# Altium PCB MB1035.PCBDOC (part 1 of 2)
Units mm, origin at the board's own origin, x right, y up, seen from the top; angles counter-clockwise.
Board outline 66 x 97 mm, 2 copper layers (TOP, Bottom), stack 1.535 mm thick; 147 components, 174 nets, 595 pads, 205 vias.
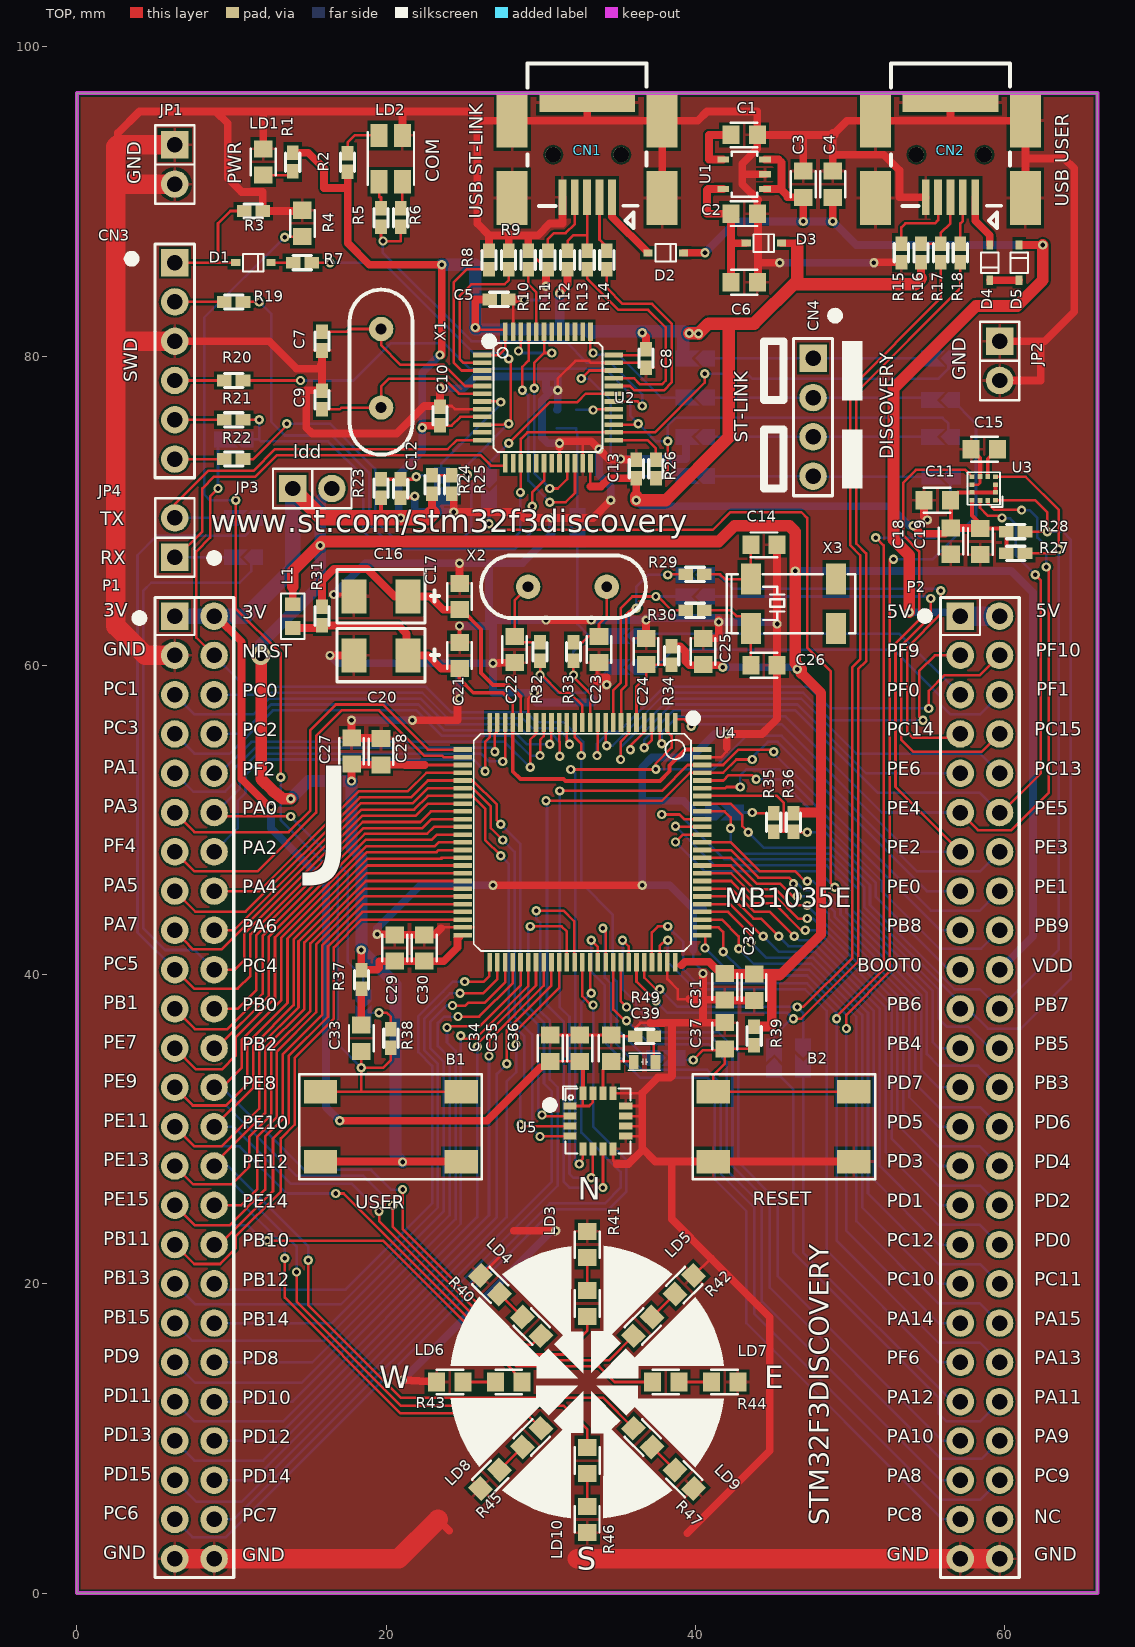
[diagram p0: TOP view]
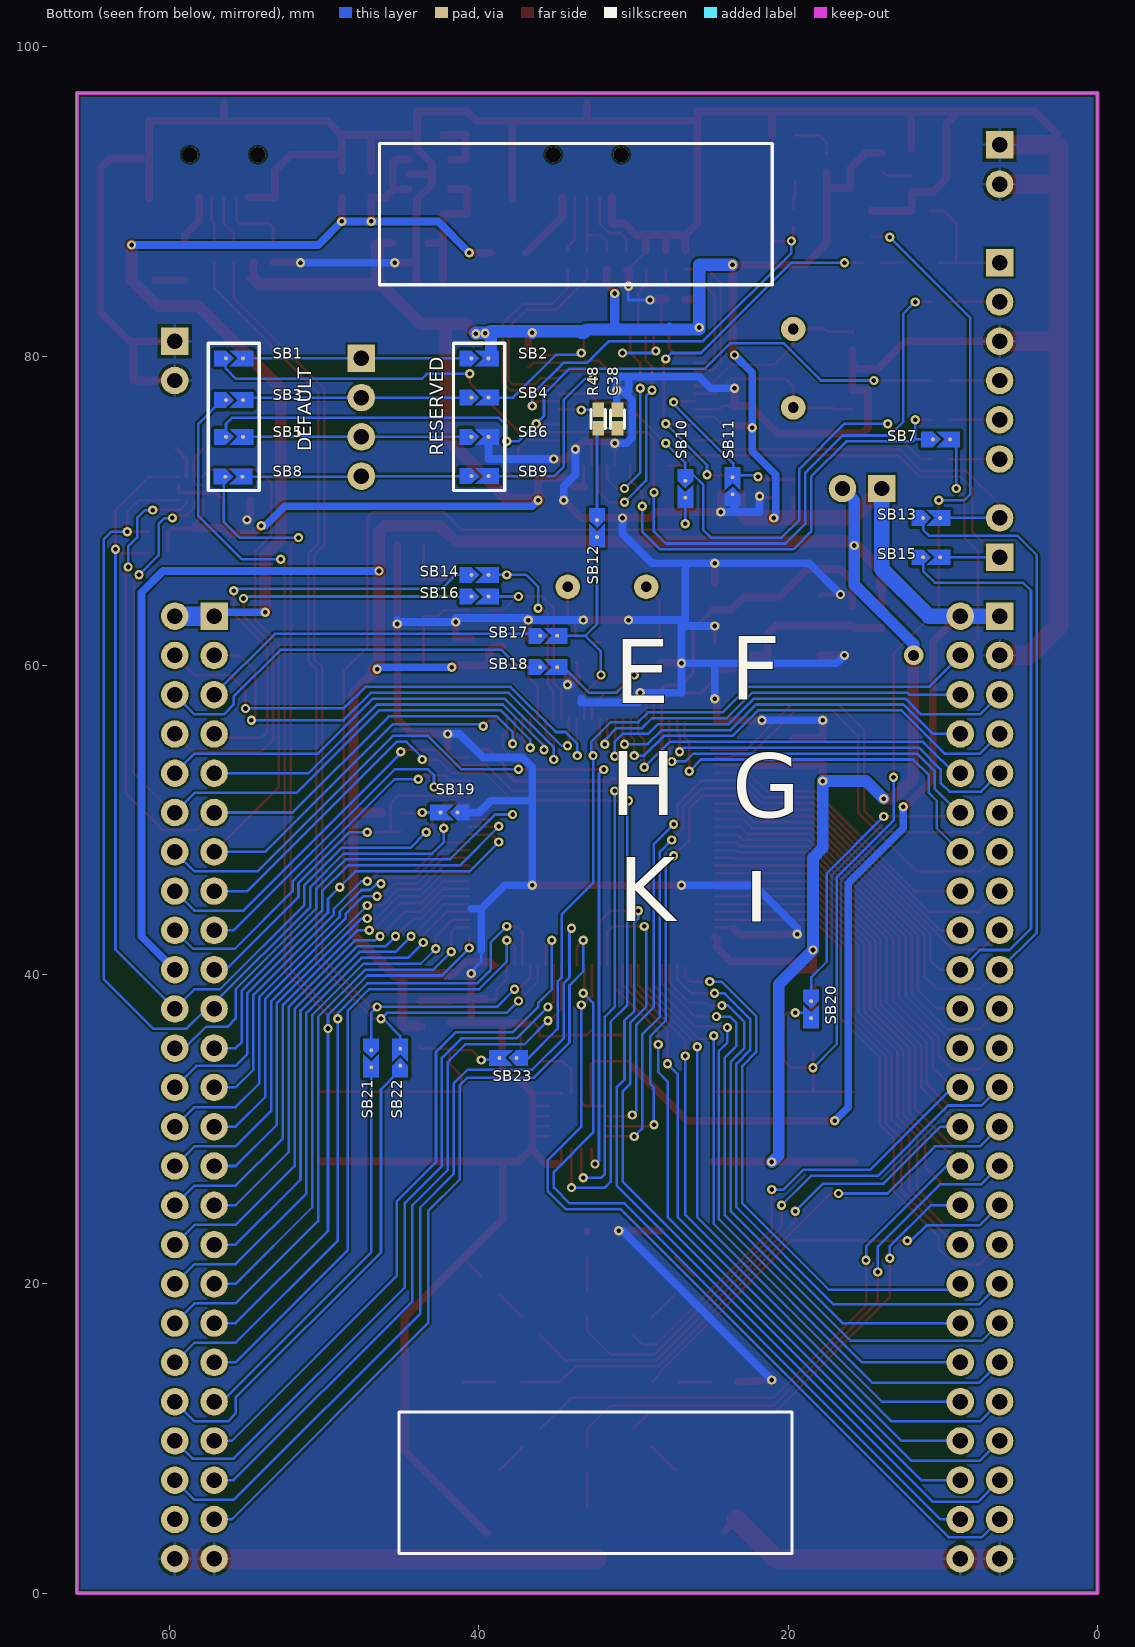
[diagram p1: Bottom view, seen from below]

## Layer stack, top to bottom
Top Mask: solder mask 0.0102, Solder Resist, Dk 3.5
TOP: signal copper 0.035
Dielectric 1: dielectric 1.465, FR-4, Dk 4.8
Bottom: signal copper 0.035
Bottom Solder: solder mask 0.0102, Solder Resist, Dk 3.5

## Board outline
0,0 66,0 66,97 0,97

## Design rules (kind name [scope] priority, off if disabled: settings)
Clearance [All] p1: gap=0.127 ignorepadtopadclearanceinfootprint=FALSE except(0: Arc-Hole Track-Hole SMDPad-Hole THPad-Hole Via-Hole Fill-Hole Poly-Hole Region-Hole Text-Hole; 0.2: SMDPad-Fill SMDPad-Poly SMDPad-Region Fill-Fill Fill-Poly Fill-Region Poly-Poly Poly-Region Region-Region)
ComponentClearance [All] p1: gap=0.2 collisioncheckmode=3 verticalgap=0.2 showdistances=FALSE
HoleSize [All] p1: absolutevalues=TRUE maxlimit=10 minlimit=0.025 maxpercent=80.000 minpercent=20.000
MinimumSolderMaskSliver [All] p1: minsoldermaskwidth=0.1
PlaneConnect [All] p1: planeconnectstyle=Relief reliefexpansion=0.508 reliefentries=4 reliefconductorwidth=0.21 reliefairgap=0.21
PolygonConnect PolygonConnect_via [IsVia] p1: connectstyle=Direct reliefconductorwidth=0.254 reliefentries=4 polygonreliefangle="90 Angle" airgapwidth=0.254
PolygonConnect [All] p2: connectstyle=Relief reliefconductorwidth=0.2 reliefentries=4 polygonreliefangle="90 Angle" airgapwidth=0.2
RoutingVias [All] p1: holewidth=0.3 width=0.8 viastyle="Through Hole" minholewidth=0.3 minwidth=0.8 maxholewidth=0.3 maxwidth=0.8
SilkToSilkClearance [All] p1: silktosilkclearance=0.2
SilkToSolderMaskClearance [IsPad] p1: minsilkscreentomaskgap=0 clearancetoexposedcopper=TRUE
SolderMaskExpansion [All] p1: expansion=0.102
Width [All] p1: maxlimit=1.27 minlimit=0.127 preferedwidth=0.2 minimp=50.000000 maximp=50.000000 favimp=50.000000
24 further rules are at their usual default settings.

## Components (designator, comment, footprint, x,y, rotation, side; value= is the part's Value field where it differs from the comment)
B1 "SW-PUSH-CMS" BP1CMS 20.3,30.16 r90 top
B2 "SW-PUSH-CMS" BP1CMS 45.7,30.16 r270 top
C1 "10nF_X7R_0603" 0603C 43.151,94.3 r180 top value=10NF
C2 "100nF" 0603C 43.151,89.212 r180 top
C3 "1µF_X5R_0603" 0603C 46.967,91.12 r270 top value=1µF
C4 "100nF" 0603C 48.875,91.12 r270 top
C5 "100nF" 0402C 27.285,83.665 r270 top
C6 "1µF_X5R_0603" 0603C 43.151,84.767 r0 top value=1µF
C7 "33pF" 0402C 15.855,80.96 r180 top value=20pF
C8 "100nF" 0402C 36.81,79.855 r0 top
C9 "33pF" 0402C 15.855,77.15 r0 top value=20pF
C10 "100nF" 0402C 23.475,76.134 r0 top
C11 "100nF" 0603C 55.633,70.675 r180 top
C12 "100nF" 0402C 20.935,71.435 r180 top
C13 "100nF" 0402C 36.175,72.705 r0 top
C14 "6.8pF" 0603C 44.43,67.79 r0 top
C15 "220nF" 0603C 58.681,73.977 r0 top value=100nF
C16 "1uF" TAN-B 19.665,64.45 r180 top value=10uF
C17 "100nF" 0603C 24.745,64.45 r270 top
C18 "10uF" 0603C 56.522,68.033 r90 top value=100nF
C19 "100nF" 0603C 58.427,68.008 r90 top
C20 "1uF" TAN-B 19.665,60.64 r180 top value=10uF
C21 "100nF" 0603C 24.745,60.64 r270 top
C22 "20pF" 0603C 28.301,61.021 r90 top
C23 "20pF" 0603C 33.762,61.021 r90 top
C24 "1uF" 0603C 36.81,60.894 r90 top
C25 "100nF" 0603C 40.493,60.894 r270 top
C26 "6.8pF" 0603C 44.43,60.005 r0 top
C27 "100nF" 0603C 17.76,54.455 r270 top
C28 "100nF" 0603C 19.665,54.417 r270 top
C29 "100nF" 0603C 20.554,41.717 r270 top
C30 "100nF" 0603C 22.459,41.717 r270 top
C31 "100nF" 0603C 41.89,39.215 r270 top
C32 "100nF" 0603C 43.795,39.177 r270 top
C33 "100nF" 0603C 18.395,35.875 r90 top
C34 "10uF" 0603C 30.614,35.242 r270 top value=100nF
C35 "100nF" 0603C 32.519,35.242 r270 top
C36 "10nF/25V" 0603C 34.551,35.242 r270 top value=100nF
C37 "100nF" 0603C 41.89,36.04 r270 top
C38 "20pF" 0402C 31.044,75.931 r0 bottom
C39 "Capacitor" C0603 36.71,34.353 r0 top value=470nF
CN1 "5075BMR-05-SM" USB-MINI-B-SMD 33,93.025 r0 top
CN2 "5075BMR-05-SM" USB-MINI-B-SMD 56.495,93.025 r0 top
CN3 "Header 6" HDR1X6 6.33,86.04 r270 top
CN4 "Header 4" "HEADER 4" 47.605,79.855 r270 top
D1 "BAT60JFILM" SOD323/A 11.41,86.04 r180 top
D2 "BAT60JFILM" SOD323/A 38.08,86.675 r180 top
D3 "BAT60JFILM" SOD323/A 44.423,87.304 r180 top
D4 "BAT60JFILM" SOD323/A 59.035,86.04 r90 top
D5 "BAT60JFILM" SOD323/A 60.94,86.04 r270 top
JP1 "" SIP2/2.54 6.33,93.66 r270 top
JP2 "" SIP2/2.54 59.67,80.96 r270 top
JP3 "" SIP2/2.54 13.95,71.435 r0 top
JP4 "JP2" SIP2/2.54 6.33,66.99 r90 top
L1 "fcm1608-0603" 0603L 13.95,63.18 r270 top value=100uH
LD1 "RED" 0603D 12.045,92.555 r90 top
LD2 "LD_BICOLOR_CMS" HSMF-A201 20.3,92.771 r270 top
LD3 "Red" 0603D 33,22.54 r90 top
LD4 "Blue" 0603D 26.714,19.936 r135 top
LD5 "Orange" 0603D 39.286,19.936 r45 top
LD6 "Green" 0603D 24.11,13.65 r180 top
LD7 "Green" 0603D 41.89,13.65 r0 top
LD8 "Orange" 0603D 26.714,7.364 r225 top
LD9 "Blue" 0603D 39.286,7.364 r315 top
LD10 "Red" 0603D 33,4.76 r270 top
P1 "Header 25X2" HEAD25X2/2.54 7.6,32.7 r270 top
P2 "Header 25X2" HEAD25X2/2.54 58.4,32.7 r270 top
R1 "1K" 0402R 13.953,92.555 r180 top
R2 "0" 0402R 17.506,92.517 r0 top
R3 "10K" 0402R 11.41,89.38 r90 top
R4 "220K" 0603R 14.585,88.58 r270 top value=10K
R5 "100" 0402R 19.665,88.961 r180 top
R6 "100" 0402R 20.936,88.955 r180 top
R7 "100" 0402R 14.585,86.04 r90 top
R8 "10K" 0402R 26.65,86.205 r0 top
R9 "10K" 0402R 27.92,86.205 r0 top
R10 "100K" 0402R 29.19,86.205 r0 top
R11 "100K" 0402R 30.46,86.205 r0 top
R12 "1K5" 0402R 31.73,86.205 r0 top
R13 "0" 0402R 33,86.205 r0 top value=1K5
R14 "0" 0402R 34.27,86.205 r0 top value=1K5
R15 "100K" 0402R 53.32,86.675 r0 top
R16 "1K5" 0402R 54.59,86.675 r0 top
R17 "22" 0402R 55.86,86.675 r0 top value=1K5
R18 "22" 0402R 57.13,86.675 r0 top value=1K5
R19 "22" 0402R 10.14,83.5 r90 top
R20 "22" 0402R 10.14,78.42 r90 top
R21 "22" 0402R 10.14,75.88 r90 top
R22 "22" 0402R 10.14,73.34 r90 top
R23 "100K" 0402R 19.665,71.435 r0 top
R24 "4K7" 0402R 22.967,71.689 r180 top
R25 "4K7" 0402R 24.237,71.689 r180 top
R26 "100" 0402R 37.445,72.705 r0 top
R27 "10K" 0402R 60.713,67.246 r90 top
R28 "10K" 0402R 60.713,68.643 r90 top
R29 "0" 0402R 39.985,65.885 r90 top value=1K5
R30 "0" 0402R 39.985,63.561 r90 top value=1K5
R31 "0" 0402R 15.855,63.18 r0 top value=1K
R32 "220" 0402R 29.952,60.894 r180 top value=1K5
R33 "0" 0402R 32.111,60.894 r180 top value=1K5
R34 "0" 0402R 38.461,60.64 r180 top value=1K
R35 "510" 0402R 45.065,49.845 r0 top value=10K
R36 "10K" 0402R 46.335,49.845 r0 top
R37 "100" 0402R 18.395,39.685 r180 top value=330
R38 "330" 0402R 20.3,35.875 r0 top
R39 "100K" 0402R 43.795,36.04 r180 top
R40 "680" 0603R 29.408,17.242 r315 top value=1K
R41 "680" 0603R 33,18.73 r270 top value=1K
R42 "680" 0603R 36.592,17.242 r225 top value=1K
R43 "510" 0603R 27.92,13.65 r0 top value=1K
R44 "510" 0603R 38.08,13.65 r180 top value=1K
R45 "680" 0603R 29.408,10.058 r45 top value=1K
R46 "680" 0603R 33,8.57 r90 top value=1K
R47 "680" 0603R 36.592,10.058 r135 top value=1K
R48 "100" 0402R 32.289,75.918 r180 bottom
R49 "10K" 0402R 36.71,36.004 r270 top
SB1 "Circuit Breaker" JP2_SMD 55.86,79.855 r180 bottom
SB2 "Circuit Breaker" JP2_SMD 39.985,79.855 r180 bottom
SB3 "Circuit Breaker" JP2_SMD 55.86,77.15 r180 bottom
SB4 "Circuit Breaker" JP2_SMD 39.985,77.315 r180 bottom
SB5 "Circuit Breaker" JP2_SMD 55.86,74.775 r180 bottom
SB6 "Circuit Breaker" JP2_SMD 39.985,74.775 r180 bottom
SB7 "Circuit Breaker" JP2_SMD 10.14,74.61 r180 bottom
SB8 "Circuit Breaker" JP2_SMD 55.896,72.196 r180 bottom
SB9 "Circuit Breaker" JP2_SMD 39.985,72.235 r180 bottom
SB10 "Circuit Breaker" JP2_SMD 26.65,71.435 r270 bottom
SB11 "Circuit Breaker" JP2_SMD 23.602,71.562 r90 bottom
SB12 "Circuit Breaker" JP2_SMD 32.365,68.895 r270 bottom
SB13 "Circuit Breaker" JP2_SMD 10.775,69.53 r180 bottom
SB14 "Circuit Breaker" JP2_SMD 39.985,65.847 r180 bottom
SB15 "Circuit Breaker" JP2_SMD 10.775,66.99 r180 bottom
SB16 "Circuit Breaker" JP2_SMD 39.985,64.45 r180 bottom
SB17 "Circuit Breaker" JP2_SMD 35.54,61.91 r180 bottom
SB18 "Circuit Breaker" JP2_SMD 35.54,59.878 r180 bottom
SB19 "Circuit Breaker" JP2_SMD 41.89,50.48 r0 bottom
SB20 "Circuit Breaker" JP2_SMD 18.522,37.78 r270 bottom
SB21 "Circuit Breaker" JP2_SMD 46.97,34.605 r270 bottom
SB22 "Circuit Breaker" JP2_SMD 45.092,34.607 r90 bottom
SB23 "Circuit Breaker" JP2_SMD 38.08,34.605 r0 bottom
U1 "LD3985M33R" SOT-23-5L 43.151,91.756 r180 top
U2 "STM32F103CBT6" ICC_LQFP48_7X7_P050 30.46,77.315 r270 top
U3 "LSM303AGR" ICC_LGA12_2X2_P050 58.654,71.435 r180 top
U4 "STM32F303VCT6" ICC_LQFP100_14X14_P050 32.689,48.552 r180 top
U5 "I3G4250D" ICC_LGA16_4X4_P065_H1P1 33.696,30.525 r0 top
X1 "8MHz" XTAL1 19.665,76.68 r90 top
X2 "8MHz" XTAL1 29.19,65.085 r0 top
X3 "MC306-G-06Q-32.768" MC306-CRYSTAL 46.335,63.98 r0 top

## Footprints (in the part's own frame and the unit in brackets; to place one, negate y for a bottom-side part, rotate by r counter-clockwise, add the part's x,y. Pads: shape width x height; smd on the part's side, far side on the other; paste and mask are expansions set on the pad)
0402C [mil]
  rect 30x37 smd paste-3.94 mask+0: 1(0,23.62) 2(0,-23.62)
  silkscreen extent -18,-23 18,24
0402R [mil]
  rect 30x37 smd paste-3.94 mask+0: 1(0,23.62) 2(0,-23.62)
  silkscreen extent -18,-23 18,24
0603C [mm]
  rect 1.1x1.2 smd paste-0.1 mask+0: 1(-0.85,0) 2(0.85,0)
  silkscreen extent -0.85,-0.8 0.86,0.8
0603D [mm]
  rect 1.1x1.2 smd paste-0.1 mask+0: 1(-0.85,0) 2(0.85,0)
  silkscreen extent -0.86,-0.8 0.84,0.8
0603L [mil]
  rect 35x40 smd paste-3.94 mask+0: 1(-30,0) 2(30,0)
  silkscreen extent -58,-30 58,30
0603R [mm]
  rect 1.1x1.2 smd paste-0.1 mask+0: 1(-0.85,0) 2(0.85,0)
  silkscreen extent -0.85,-0.8 0.86,0.8
BP1CMS [mm]
  rect 1.52x2.16 smd paste-0.1 mask+0: 1(-2.25,-4.55) 2(2.25,-4.55) 3(2.25,4.55) 4(-2.25,4.55)
  silkscreen extent -3.4,-5.88 3.4,5.92
C0603 [mm]
  rect 0.64x0.89 smd mask+0.05: 1(-0.7,0) 2(0.7,0)
  silkscreen extent -1.05,-0.55 1.02,0.55, body extent -0.9,-0.5 0.9,0.5, height 1.4
HDR1X6 [mil]
  rect 70x70 / inner round 0 / far side rect 70x70 hole 39.37 paste+0 mask+0: 1(0,0)
  round 70 / inner round 0 / far side round 70 hole 39.37 paste+0 mask+0: 2(100,0) 3(200,0) 4(300,0) 5(400,0) 6(500,0)
  silkscreen extent -48,-50 548,50
HEAD25X2/2.54 [mil]
  rect 70x70 / inner round 0 / far side rect 70x70 hole 39.37 paste+0 mask+0: 1(-1200,-50)
  round 70 / inner round 0 / far side round 70 hole 39.37 paste+0 mask+0: 2(-1200,50) 3(-1100,-50) 4(-1100,50) 5(-1000,-50) 6(-1000,50) 7(-900,-50) 8(-900,50) 9(-800,-50) 10(-800,50) 11(-700,-50) 12(-700,50) 13(-600,-50) 14(-600,50) 15(-500,-50) 16(-500,50) 17(-400,-50) 18(-400,50) 19(-300,-50) 20(-300,50) 21(-200,-50) 22(-200,50) 23(-100,-50) 24(-100,50) 25(0,-50) 26(0,50) 27(100,-50) 28(100,50) 29(200,-50) 30(200,50) 31(300,-50) 32(300,50) 33(400,-50) 34(400,50) 35(500,-50) 36(500,50) 37(600,-50) 38(600,50) 39(700,-50) 40(700,50) 41(800,-50) 42(800,50) 43(900,-50) 44(900,50) 45(1000,-50) 46(1000,50) 47(1100,-50) 48(1100,50) 49(1200,-50) 50(1200,50)
  silkscreen extent -1248,-101 1248,100
"HEADER 4" [mil]
  rect 70x70 / inner round 0 / far side rect 70x70 hole 39.37 paste+0 mask+0: 1(0,0)
  round 70 / inner round 0 / far side round 70 hole 39.37 paste+0 mask+0: 2(100,0) 3(200,0) 4(300,0)
  silkscreen extent -50,-50 350,50
HSMF-A201 [mm]
  rect 1.5x1.1 smd paste-0.1 mask+0: 1(-1.5,0.75) 2(1.5,0.75) 3(1.5,-0.75) 4(-1.5,-0.75)
  silkscreen extent -1.7,-1.5 1.7,1.5
ICC_LGA12_2X2_P050 [mm] "MCD-00709"
  rect 0.325x0.3 smd mask+0.05: 1(-0.763,0.75) 2(-0.763,0.25) 3(-0.763,-0.25) 4(-0.763,-0.75) 7(0.763,-0.75) 8(0.763,-0.25) 9(0.763,0.25) 10(0.763,0.75)
  rect 0.3x0.325 smd mask+0.05: 5(-0.25,-0.762) 6(0.25,-0.762) 11(0.25,0.763) 12(-0.25,0.763)
  silkscreen extent -1.2,-1.05 1.05,1.2, body extent -1.05,-1.05 1.05,1.05, height 1.01
ICC_LGA16_4X4_P065_H1P1 [mm] "MCD-01963"
  rect 0.85x0.45 smd mask+0.05: 1(-1.8,0.975) 2(-1.8,0.325) 3(-1.8,-0.325) 4(-1.8,-0.975) 9(1.8,-0.975) 10(1.8,-0.325) 11(1.8,0.325) 12(1.8,0.975)
  rect 0.45x0.85 smd mask+0.05: 5(-0.975,-1.8) 6(-0.325,-1.8) 7(0.325,-1.8) 8(0.975,-1.8) 13(0.975,1.8) 14(0.325,1.8) 15(-0.325,1.8) 16(-0.975,1.8)
  silkscreen extent -2.25,-2.1 2.1,2.25, body extent -2.1,-2.1 2.1,2.1, height 1.1
ICC_LQFP48_7X7_P050 [mm]
  rect 0.3x1.2 smd mask+0.05: 1(-2.75,-4.25) 2(-2.25,-4.25) 3(-1.75,-4.25) 4(-1.25,-4.25) 5(-0.75,-4.25) 6(-0.25,-4.25) 7(0.25,-4.25) 8(0.75,-4.25) 9(1.25,-4.25) 10(1.75,-4.25) 11(2.25,-4.25) 12(2.75,-4.25) 25(2.75,4.25) 26(2.25,4.25) 27(1.75,4.25) 28(1.25,4.25) 29(0.75,4.25) 30(0.25,4.25) 31(-0.25,4.25) 32(-0.75,4.25) 33(-1.25,4.25) 34(-1.75,4.25) 35(-2.25,4.25) 36(-2.75,4.25)
  rect 1.2x0.3 smd mask+0.05: 13(4.25,-2.75) 14(4.25,-2.25) 15(4.25,-1.75) 16(4.25,-1.25) 17(4.25,-0.75) 18(4.25,-0.25) 19(4.25,0.25) 20(4.25,0.75) 21(4.25,1.25) 22(4.25,1.75) 23(4.25,2.25) 24(4.25,2.75) 37(-4.25,2.75) 38(-4.25,2.25) 39(-4.25,1.75) 40(-4.25,1.25) 41(-4.25,0.75) 42(-4.25,0.25) 43(-4.25,-0.25) 44(-4.25,-0.75) 45(-4.25,-1.25) 46(-4.25,-1.75) 47(-4.25,-2.25) 48(-4.25,-2.75)
  silkscreen extent -3.52,-3.52 3.52,3.52, body extent -4.5,-4.5 4.5,4.5, height 1.6
ICC_LQFP100_14X14_P050 [mm]
  rect 0.3x1.2 smd mask+0.05: 1(-6,-7.75) 2(-5.5,-7.75) 3(-5,-7.75) 4(-4.5,-7.75) 5(-4,-7.75) 6(-3.5,-7.75) 7(-3,-7.75) 8(-2.5,-7.75) 9(-2,-7.75) 10(-1.5,-7.75) 11(-1,-7.75) 12(-0.5,-7.75) 13(0,-7.75) 14(0.5,-7.75) 15(1,-7.75) 16(1.5,-7.75) 17(2,-7.75) 18(2.5,-7.75) 19(3,-7.75) 20(3.5,-7.75) 21(4,-7.75) 22(4.5,-7.75) 23(5,-7.75) 24(5.5,-7.75) 25(6,-7.75) 51(6,7.75) 52(5.5,7.75) 53(5,7.75) 54(4.5,7.75) 55(4,7.75) 56(3.5,7.75) 57(3,7.75) 58(2.5,7.75) 59(2,7.75) 60(1.5,7.75) 61(1,7.75) 62(0.5,7.75) 63(0,7.75) 64(-0.5,7.75) 65(-1,7.75) 66(-1.5,7.75) 67(-2,7.75) 68(-2.5,7.75) 69(-3,7.75) 70(-3.5,7.75) 71(-4,7.75) 72(-4.5,7.75) 73(-5,7.75) 74(-5.5,7.75) 75(-6,7.75)
  rect 1.2x0.3 smd mask+0.05: 26(7.75,-6) 27(7.75,-5.5) 28(7.75,-5) 29(7.75,-4.5) 30(7.75,-4) 31(7.75,-3.5) 32(7.75,-3) 33(7.75,-2.5) 34(7.75,-2) 35(7.75,-1.5) 36(7.75,-1) 37(7.75,-0.5) 38(7.75,0) 39(7.75,0.5) 40(7.75,1) 41(7.75,1.5) 42(7.75,2) 43(7.75,2.5) 44(7.75,3) 45(7.75,3.5) 46(7.75,4) 47(7.75,4.5) 48(7.75,5) 49(7.75,5.5) 50(7.75,6) 76(-7.75,6) 77(-7.75,5.5) 78(-7.75,5) 79(-7.75,4.5) 80(-7.75,4) 81(-7.75,3.5) 82(-7.75,3) 83(-7.75,2.5) 84(-7.75,2) 85(-7.75,1.5) 86(-7.75,1) 87(-7.75,0.5) 88(-7.75,0) 89(-7.75,-0.5) 90(-7.75,-1) 91(-7.75,-1.5) 92(-7.75,-2) 93(-7.75,-2.5) 94(-7.75,-3) 95(-7.75,-3.5) 96(-7.75,-4) 97(-7.75,-4.5) 98(-7.75,-5) 99(-7.75,-5.5) 100(-7.75,-6)
  silkscreen extent -7.02,-7.02 7.02,7.02, body extent -8,-8 8,8, height 1.61
JP2_SMD [mil]
  round 10 smd paste-3.94 mask+0: 1(-19.68,0) 2(23.62,0)
  TOP region: -9.84,-19.69 49.21,-19.69 49.21,19.68 -9.84,19.68 9.84,0
  TOP region: -19.68,19.68 -49.21,19.68 -49.21,-19.69 -19.68,-19.69 0,0
MC306-CRYSTAL [mm]
  rect 1.3x2 smd paste-0.1 mask+0: 1(-2.75,-1.6) 2(2.75,-1.6) 3(2.75,1.6) 4(-2.75,1.6)
  silkscreen extent -4.3,-1.9 4,1.9
SIP2/2.54 [mil]
  rect 70x70 / inner round 0 / far side rect 70x70 hole 39.37 paste+0 mask+0: 1(0,0)
  round 70 / inner round 0 / far side round 70 hole 39.37 paste+0 mask+0: 2(100,0)
  silkscreen extent -50,-50 150,50
SOD323/A [mm]
  rect 0.6x0.45 smd paste-0.1 mask+0: 1(1.143,0) 2(-1.143,0)
  silkscreen extent -0.67,-0.57 0.67,0.57
SOT-23-5L [mil]
  rect 30x16 smd paste-3.94 mask+0: 1(-53.15,37.4) 2(-53.15,0) 3(-53.15,-37.4) 4(53.15,-37.4) 5(53.15,37.4)
  silkscreen extent -33,-58 32,57
TAN-B [mm]
  rect 1.6x2.2 smd paste-0.1 mask+0: 1(-1.75,0) 2(1.75,0)
  silkscreen extent -3.75,-1.75 2.85,1.7
USB-MINI-B-SMD [mm]
  rect 2x3.5 smd paste-0.1 mask+0: 0(-4.853,-2.8) 0(-4.853,2.2) 0(4.847,-2.8) 0(4.847,2.2)
  rect 6.2x1.2 smd paste-0.1 mask+0: 0(0,3.35)
  rect 0.508x2.3 smd paste-0.1 mask+0: 1(1.597,-2.75) 2(0.797,-2.75) 3(-0.003,-2.75) 4(-0.803,-2.75) 5(-1.603,-2.75)
  round 1 / inner round 0 / far side round 1 hole 1 unplated paste+0 mask+0: 11(2.194,0) 12(-2.2,0)
  silkscreen extent -3.85,-4.76 3.85,5.9
XTAL1 [mm]
  round 1.575 / inner round 0 / far side round 1.575 hole 0.7 paste+0 mask+0: 1(-0.009,-0.005) 2(5.071,-0.005)
  silkscreen extent -3.06,-2.04 7.61,2.03

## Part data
B1 B2: "Non-Open Push-Button 0.1A 24V", Manuf_1=FARNELL, Manuf_Part_1=535-930
C1: library part "CAP SMD 0603  X7R 10000PF 50V 10%", "0603  X7R 10NF", Rated voltage=50V, Temperature Max=+125°C, Temperature Min=-55°C, Tolerance=10%
C2 C4 C5 C7 C8 C9 C10 C12 C13 C17 C21 C25 C27 C28 C29 C30 C31 C32 C38: library part Cap, "Capacitor"
C3 C6: library part "CAP SMD 0603  X5R 1µF 25V 10%", "0603  X5R 1µF", Rated voltage=25V, Temperature Max=+125°C, Temperature Min=-55°C, Tolerance=10%
C11 C14 C15 C18 C19 C22 C23 C24 C26 C33 C34 C35 C36 C37: library part CAP, "Capacitor"
C16 C20: library part "Cap Pol1", "Polarized Capacitor (Radial)"
C39: library part MCD-01006, "Capacitor, MLCC, 470nF, 16V, X7R, 10%, 0603, T=0.8mm", Manufacturer=YAGEO, Manufacturer_Part_Number=CC0603KRX7R7BB474, Package=C0603
CN1 CN2: library part "USB-MINI-typeB connector"
CN3: "Header, 6-Pin"
CN4: "Header, 4-Pin"
D1 D2 D3 D4 D5: Manuf_1=STM
JP1 JP2 JP3: library part JP2
L1: library part Inductor, "Inductor"
LD1: library part PHOTO
LD2: "Bicolor Led", Manuf_1="Avago Technologies", Manuf_Part_1=HSMF-A201-A00J1
LD3 LD4 LD5 LD6 LD7 LD8 LD9 LD10: library part LED2, "Typical RED, GREEN, YELLOW, AMBER GaAs LED"
P1 P2: "Header, 25-Pin, Dual row"
R1 R2 R3 R4 R5 R6 R7 R8 R9 R10 R11 R12 R13 R14 R15 R16 R17 R18 R19 R20 R21 R22 R23 R24 R25 R26 R27 R28 R29 R30 R32 R33 R35 R36 R37 R38 R39 R48 R49: library part res1, "Resistor"
R31 R34 R40 R41 R42 R43 R44 R45 R46 R47: library part Res1, "Resistor"
U1: "Ultra low drop-low noise BiCMOS voltage, regulators low ESR capacitors compatible", Manuf_1=STM
U2: "Medium-density performance line ARM-based 32-bit MCU with 128KB Flash", Manuf_1=STM
U3: library part MCD-00709, "3D accelerometer and 3D magnetometer", Manufacturer=STMICROELECTRONICS
U4: "STM32F303VCT6 (Manta-Edge)", Manuf_1=STM
U5: library part MCD-01963, "MEMS motion sensor: 3-axis digital output gyroscope LG4-16 4x4mm", Manufacturer=STMICROELECTRONICS, Package=LGA-16
X1 X2: library part XTAL, "Crystal Oscillator"
X3: library part MC306

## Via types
v1: diameter 0.6, hole 0.3, TOP to Bottom, tented both sides, 204 vias
v2: diameter 1.27, hole 0.7, TOP to Bottom, tented both sides, 1 vias

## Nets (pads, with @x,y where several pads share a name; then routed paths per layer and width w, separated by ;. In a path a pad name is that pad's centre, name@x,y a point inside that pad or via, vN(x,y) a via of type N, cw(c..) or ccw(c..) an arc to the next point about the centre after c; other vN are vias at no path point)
3V: C5.2 C8.1 C10.2 C11.1 C13.2 C18.2 C19.2 C34.2 C35.2 D3.2 JP3.1 P1.1 P1.2 R1.2 R2.2 R12.2 R16.2 R23.2 R24.1 R27.1 R28.1 SB2.2 U2.1 U2.9 U2.24 U2.36 U2.48 U3.2 U3.3 U3.9 U3.10 U5.1 U5.15 U5.16 | length 239.1
  TOP w0.165: 19.665,69.53 19.665,69.784 ; C10.2@23.475,75.499 24.237,75.499 24.803,76.065 U2.9@26.06,76.065 ; v1@25.868,81.76 25.913,81.715 27.71,81.715 27.71,80.49 27.285,80.065 U2.1@26.06,80.065 ; 29.979,33.997 30.374,34.392 C34.2@30.614,34.392 32.453,34.392 C35.2@32.453,34.462 ; U5.1@31.896,31.5 32.721,31.5 ; C35.2@32.519,34.392 C35.2@32.721,34.19 ; U5.16@32.721,32.325 32.721,31.5 ; 33.21,71.562 U2.24@33.21,72.915 ; U5.15@33.371,32.325 33.371,31.744 33.127,31.5 32.721,31.5 ; U2.36@34.86,80.065 36.42,80.065 C8.1@36.81,80.455
  TOP w0.25: 19.665,69.784 R23.2@19.665,70.835
  TOP w0.254: U5.16@32.721,32.325 C35.2@32.721,34.19 ; C18.2@56.522,68.883 56.522,70.636 C11.1@56.483,70.675 56.993,71.185 U3.9@57.892,71.185 U3.2@59.417,71.185 U3.3@59.417,71.685 ; U3.10@57.892,70.685 57.892,69.686 58.427,69.151 C19.2@58.427,68.858 ; C19.2@58.402,68.883 C19.2@58.427,68.858 ; R27.1@60.113,67.5 R28.1@60.113,68.643 59.898,68.858 C19.2@58.427,68.858
  TOP w0.5: P1.2@8.87,63.18 8.997,63.18 10.648,61.529 10.648,52.639 12.426,50.861 v1(12.553,50.861) ; R1.2@13.953,93.155 14.966,93.155 15.982,92.139 15.982,90.866 17.506,90.866 ; v1(16.998,30.541) 26.523,30.541 29.979,33.997 ; R2.2@17.506,91.917 17.506,90.866 ; v1(22.332,75.372) 22.332,75.499 23.475,75.499 C10.2@23.475,75.534 ; 22.967,69.834 R24.1@22.967,71.089 ; v1(23.475,80.071) 23.602,80.071 v1(23.602,85.913) 18.903,85.913 17.506,87.31 17.506,90.866 ; v1(25.761,81.849) 25.761,81.76 25.868,81.76 25.77,81.858 25.761,81.867 25.761,83.665 C5.2@26.685,83.665 ; v1@31.222,84.135 31.73,84.643 R12.2@31.73,85.605 ; 33.21,71.562 33.889,71.562 34.432,72.105 C13.2@36.175,72.105 v1@36.175,70.927 ; v1(36.556,81.506) 36.81,81.252 C8.1@36.81,80.455 ; D3.2@45.566,87.304 46.589,87.304 46.589,87.183 ; v1(54.082,69.022) 54.588,68.516 56.155,68.516 C18.2@56.522,68.883 C19.2@58.402,68.883 ; 54.59,85.024 R16.2@54.59,86.075
  TOP w0.6: v1(31.222,84.046) v1@31.222,84.135
  TOP w0.8: v1@36.175,70.927 v1(36.175,70.673) 38.08,70.673 42.144,74.737 42.144,82.1 ; v1(39.604,81.468) 40.196,81.468 v1(40.196,81.45) 40.847,82.1 42.144,82.1 ; 46.589,87.183 46.589,84.894 ; 54.59,85.024 54.209,84.643 46.589,84.643 46.589,84.894 ; 42.144,82.1 43.795,82.1 46.589,84.894
  TOP w1: JP3.1@13.95,71.435 15.855,69.53 19.665,69.53 v1(20.935,69.53) 22.663,69.53 22.967,69.834
  Bottom w0.165: 27.666,81.76 27.71,81.716
  Bottom w0.5: v1(12.553,50.861) 12.553,49.464 16.109,45.908 16.109,31.43 v1(16.998,30.541) ; v1(20.935,69.53) 20.808,69.53 20.808,72.324 22.332,73.848 v1(22.332,75.372) 22.332,78.928 v1(23.475,80.071) ; v1(36.175,70.673) 36.556,70.292 52.558,70.292 53.828,69.022 v1(54.082,69.022)
  Bottom w0.6: 31.222,81.76 v1(31.222,84.046)
  Bottom w0.8: v1(23.602,85.913) 25.761,85.913 v1(25.761,81.849) 25.761,81.722 27.666,81.722 27.666,81.76 ; 27.71,81.716 27.71,81.722 31.222,81.722 ; 31.222,81.76 31.222,81.722 ; v1(36.556,81.506) v1@36.556,81.595 ; SB2.2@39.385,79.855 39.223,79.855 39.223,81.468 ; v1(39.604,81.468) 39.223,81.468 ; 31.222,81.722 33.071,81.722 33.071,81.633 ; 33.071,81.633 33.207,81.633 33.34,81.5 ; 33.071,81.633 33.204,81.5 33.34,81.5 ; 33.34,81.5 33.396,81.506 33.396,81.595 v1@36.556,81.595 ; v1@36.556,81.595 39.255,81.595 v1@39.35,81.5 ; 39.147,81.5 39.179,81.468 39.223,81.468 ; 39.147,81.5 39.223,81.5 39.223,81.468 ; 39.147,81.5 39.096,81.5 39.146,81.5 ; 39.146,81.5 v1@39.35,81.5 ; v1@39.35,81.5 v1@40.196,81.5 ; v1@40.196,81.5 40.247,81.5 v1(40.196,81.45) v1@40.196,81.5
  Bottom w1: P1.1@6.584,63.18 P1.2@8.616,63.18 ; P1.2@8.87,63.18 10.902,63.18 13.95,66.228 JP3.1@13.95,71.435
  Bottom w1.27: P1.1@6.33,63.18 P1.1@6.584,63.18 ; P1.2@8.616,63.18 P1.2@8.87,63.18
5V: C3.2 C4.2 D2.2 D5.2 P2.1 P2.2 U1.1 U1.3 | length 70.9
  TOP w0.5: D2.2@39.223,86.675 v1(40.62,86.675) ; U1.1@44.501,90.806 45.506,90.806 45.573,90.739 ; U1.3@44.501,92.706 45.384,92.706 45.573,92.517 45.573,90.739 ; v1(46.97,88.707) 46.97,90.27 45.954,90.27 45.954,90.358 45.573,90.739 ; v1(48.875,88.707) C4.2@48.875,90.27 ; D5.2@60.94,87.183 v1(62.464,87.183)
  TOP w0.762: v1(53.828,63.434) 53.828,67.117 52.812,68.133 52.812,77.912 58.146,83.246 60.813,83.246 62.464,84.897 v1(62.464,87.183)
  Bottom w0.5: v1(40.62,86.675) 42.652,88.707 v1(46.97,88.707) v1(48.875,88.707) 50.399,87.183 v1(62.464,87.183) ; v1(53.828,63.434) 57.13,63.434 P2.1@57.13,63.18
  Bottom w1.27: P2.1@57.13,63.18 P2.2@59.67,63.18
AIN_1: R7.2 R24.2 R25.2 U2.10 | length 28.3
  TOP w0.165: R7.2@15.185,86.04 v1(16.363,86.04) ; R24.2@22.967,72.289 R25.2@24.237,72.289 25.218,72.289 25.218,72.324 v1(25.253,72.324) ; U2.10@26.06,75.565 U2.10@26.21,75.565 27.605,75.565 27.666,75.626 v1@27.793,75.626 ; v1(27.92,75.626) v1@27.793,75.626 ; v1(27.92,79.817) 28.047,79.817 28.047,75.88 v1@27.793,75.626
  Bottom w0.165: v1(16.363,86.04) 19.792,86.04 25.634,80.198 27.539,80.198 v1(27.92,79.817) ; v1(25.253,72.324) 25.253,72.959 v1(27.92,75.626)
BOOT0: P2.19 R35.2 R36.2 U4.94 | length 23.5
  TOP w0.165: U4.94@40.639,51.552 45.263,51.552 45.7,51.115 45.7,49.372 45.573,49.245 ; R35.2@45.065,49.245 45.573,49.245 ; v1(47.224,49.21) 46.335,49.21 R36.2@46.335,49.245 45.573,49.245
  Bottom w0.165: v1(47.224,49.21) 48.367,49.21 51.669,45.908 51.669,45.019 56.368,40.32 P2.19@57.13,40.32
GND: B2.2 B2.3 C1.1 C2.1 C3.1 C4.1 C5.1 C6.2 C7.1 C8.2 C9.1 C10.1 C11.2 C12.1 C13.1 C14.2 C15.1 C16.2 C17.1 C18.1 C19.1 C20.2 C21.1 C22.1 C23.1 C24.2 C25.1 C26.2 C27.1 C28.1 C29.1 C30.1 C31.2 C32.2 C34.1 C35.1 C36.1 C37.1 C38.2 CN1.0 CN1.5 CN2.0 CN2.5 CN3.3 JP1.1 JP1.2 JP2.1 JP2.2 LD1.2 LD2.1 LD3.2 LD4.2 LD5.2 LD6.2 LD7.2 LD8.2 LD9.2 LD10.2 P1.3 P1.49 P1.50 P2.49 P2.50 R3.2 R4.1 R8.1 R9.1 R10.1 R11.2 R15.2 R25.1 R49.2 SB6.2 SB11.1 SB19.1 U1.2 U2.8 U2.20 U2.23 U2.35 U2.47 U3.6 U3.8 U4.20 U4.49 U4.74 U4.99 U5.8 U5.9 U5.10 U5.11 U5.12 U5.13 | length 631.4
  TOP w0.165: C10.1@23.475,76.769 24.237,76.769 24.441,76.565 U2.8@26.06,76.565 ; 23.547,42.987 23.612,43.052 U4.49@24.739,43.052 ; LD4.2@26.113,20.537 27.319,21.744 ; C5.1@27.922,83.628 28.21,83.34 U2.47@28.21,81.715 ; U4.20@29.189,56.502 29.189,57.845 v1(29.571,58.227) ; R10.1@29.19,86.805 30.425,85.57 R11.2@30.46,85.605 ; C34.1@30.614,36.092 C35.1@32.519,36.092 ; v1(31.095,77.785) 31.095,78.547 32.238,79.69 33.127,79.69 33.252,79.565 U2.35@34.71,79.565 36.5,79.565 C8.2@36.81,79.255 ; U2.20@31.21,72.915 v1@31.21,74.102 ; U2.23@32.71,72.915 32.71,74.483 ; C35.1@32.768,36.367 33.043,36.092 C36.1@34.551,36.092 34.639,36.004 R49.2@36.11,36.004 36.11,36.547 36.438,36.875 37.086,36.875 ; 33.635,59.211 33.635,60.171 C23.1@33.762,60.171 ; U5.13@34.651,32.325 U5.13@34.671,32.325 36.55,32.325 36.556,32.319 ; U5.8@34.671,28.725 34.671,27.981 34.905,27.747 ; U5.9@35.496,29.55 36.556,29.55 ; U5.10@35.496,30.2 36.556,30.2 ; U5.11@35.496,30.85 36.556,30.85 ; U5.12@35.496,31.5 36.556,31.5 ; U4.74@38.189,40.602 38.189,39.703 38.842,39.05 38.842,38.415 39.604,38.415 ; LD5.2@39.887,20.537 41.001,21.651 ; U4.99@40.639,54.052 41.652,54.052 42.017,54.417 42.017,54.671 ; U3.8@57.892,71.685 58.294,71.685 58.404,71.795 U3.6@58.404,72.197
  TOP w0.25: v1(16.617,64.577) 17.915,64.577 C16.2@17.915,64.45 ; C12.1@20.935,70.835 21.757,70.835 v1(21.851,70.929) ; C21.1@24.745,61.49 v1(24.745,62.545)
  TOP w0.254: C15.1@57.831,73.977 58.404,73.404 U3.6@58.404,72.197
  TOP w0.5: 2.647,93.66 2.647,94.422 4.044,95.819 8.997,95.819 ; CN3.3@6.33,80.96 12.426,80.96 14.204,79.182 15.779,79.182 15.779,79.436 ; LD1.2@12.045,93.405 12.045,95.819 ; R4.1@14.585,89.43 14.585,89.38 R3.2@12.01,89.38 12.01,90.612 10.648,90.612 9.759,91.501 9.759,95.057 8.997,95.819 ; C9.1@15.855,77.75 C9.1@15.855,77.785 ; C7.1@15.855,80.36 15.855,79.512 ; v1(16.363,60.64) C20.2@17.915,60.64 ; v1(17.76,56.449) C27.1@17.76,55.305 19.665,55.305 C28.1@19.665,55.267 ; v1(19.411,42.606) 20.554,42.606 C29.1@20.554,42.567 C30.1@22.459,42.567 23.127,42.567 23.547,42.987 ; LD2.1@21.05,94.271 21.05,95.819 ; v1(21.062,13.777) LD6.2@23.26,13.65 ; v1(21.697,56.449) 24.618,56.449 24.618,57.846 v1(24.745,57.846) ; 23.348,4.76 24.071,4.037 ; C10.1@23.475,76.734 C10.1@23.475,76.769 ; R25.1@24.237,71.089 24.364,71.089 v1(24.364,69.911) 28.555,69.911 28.936,69.53 v1(30.714,69.53) 33.381,69.53 v1(34.524,70.673) ; C17.1@24.745,65.3 v1(24.745,66.609) ; R8.1@26.65,86.805 26.65,87.818 ; v1(26.904,45.781) v1(36.556,45.781) ; v1(26.904,60.132) 27.301,60.132 27.301,60.171 C22.1@28.301,60.171 ; C5.1@27.885,83.665 C5.1@27.922,83.665 ; R9.1@27.92,86.805 27.92,87.818 ; C5.1@27.922,83.628 C5.1@27.922,83.665 ; 28.243,23.429 v1(30.968,23.429) ; v1(28.936,83.627) 28.936,83.665 C5.1@27.958,83.665 ; R10.1@29.19,86.805 29.19,87.818 ; v1(30.333,62.926) v1(33.254,62.926) ; v1(30.333,84.516) 30.333,85.57 R11.2@30.425,85.57 ; v1@31.21,74.102 v1(31.21,74.356) 31.21,74.483 32.71,74.483 33.254,74.483 v1(33.762,73.975) 34.432,73.305 v1@35.159,73.305 ; CN1.5@31.397,90.275 31.397,88.58 30.587,88.58 29.825,87.818 29.19,87.818 ; LD3.2@33,23.39 LD3.2@33,23.429 ; CN1.0@33,96.375 33,95.225 ; 33.635,58.989 33.889,58.989 33.889,58.862 34.016,58.862 34.016,58.735 v1(34.27,58.735) 34.27,59.211 33.635,59.211 ; 34.905,27.747 35.667,27.747 36.556,28.636 36.556,28.763 ; v1(35.159,73.34) v1@35.159,73.305 ; C13.1@36.175,73.305 v1@35.159,73.305 ; 36.55,32.325 37.563,33.337 38.361,33.337 38.488,33.464 38.488,36.891 ; 36.556,32.319 36.556,31.5 36.556,30.85 36.556,30.2 36.556,29.55 36.556,28.763 ; C24.2@36.81,61.744 v1(36.81,62.926) ; 37.086,36.875 37.937,36.875 37.953,36.891 38.488,36.891 ; CN1.0@37.847,90.225 CN1.0@37.847,95.225 ; 39.477,3.871 44.811,9.205 44.811,17.841 41.001,21.651 38.461,24.191 38.461,27.91 ; 39.604,38.415 40.493,38.415 ; v1(40.493,40.066) 40.493,38.415 ; C25.1@40.493,61.744 41.509,61.744 v1(41.509,62.799) v1@41.509,62.926 ; C37.1@41.89,36.89 40.493,36.89 ; 42.017,54.671 v1(42.017,55.56) 44.303,55.56 44.938,56.195 45.28,56.537 v1(45.28,62.672) C14.2@45.28,67.79 ; C32.2@43.795,38.327 41.89,38.327 C31.2@41.89,38.365 40.493,38.365 ; C6.2@44.001,84.767 44.001,84.77 44.049,84.77 44.049,86.04 ; U1.2@44.501,91.756 43.033,91.756 ; v1(45.446,86.04) 44.049,86.04 ; C3.1@46.967,91.97 46.967,94.3 ; C4.1@48.875,91.97 48.875,93.025 ; B2.3@50.25,27.91 38.461,27.91 ; v1(51.542,86.04) 51.542,86.075 R15.2@53.32,86.075 ; C11.2@54.783,70.675 54.783,69.62 v1(54.998,69.405) ; CN2.5@54.892,90.275 53.193,90.275 53.193,92.009 52.177,93.025 48.875,93.025 ; CN2.0@56.495,96.375 56.495,95.225 ; JP2.2@59.67,78.42 62.337,78.42 62.337,80.96 ; JP2.1@59.67,80.96 62.337,80.96 ; CN2.0@61.342,90.225 61.342,92.771 ; 8.997,95.819 12.045,95.819 ; 12.045,95.819 21.05,95.819 ; 15.779,79.436 15.855,79.436 ; 15.779,79.436 15.855,79.512 ; C9.1@15.855,77.785 14.839,77.785 14.839,75.372 15.22,74.991 20.681,74.991 22.459,76.769 C10.1@23.475,76.769 ; C9.1@15.855,77.785 15.855,79.436 ; 15.855,79.436 15.855,79.512 ; 21.05,95.819 25.888,95.819 25.888,95.225 ; C10.1@23.475,76.769 v1(23.475,77.912) ; v1(23.475,77.912) 23.475,77.989 23.513,77.95 23.552,77.912 v1(23.475,77.912) ; 25.888,95.225 25.888,88.58 26.65,87.818 ; 25.888,95.225 CN1.0@28.147,95.225 33,95.225 ; 26.65,87.818 27.92,87.818 ; 27.92,87.818 29.19,87.818 ; C5.1@27.922,83.665 27.922,83.702 C5.1@27.958,83.665 ; C5.1@27.922,83.665 C5.1@27.958,83.665 ; 33,95.225 CN1.0@37.847,95.225 ; 36.556,28.763 37.409,27.91 38.461,27.91 ; CN1.0@37.847,95.225 40.153,95.225 40.747,95.819 44.001,95.819 C1.1@44.001,94.3 ; 38.488,36.891 40.493,36.891 ; 40.493,36.891 40.493,38.365 ; 40.493,38.365 40.493,38.415 ; 43.033,91.756 43.033,92.438 44.001,93.406 C1.1@44.001,94.3 ; 43.033,91.756 43.033,91.12 44.049,90.104 44.001,90.104 C2.1@44.001,89.212 44.049,89.212 44.049,86.04 ; C1.1@44.001,94.3 46.967,94.3 ; 46.967,94.3 48.875,94.3 ; 48.875,93.025 48.875,94.3 ; 48.875,94.3 48.88,94.3 ; 48.875,94.3 48.875,94.422 48.939,94.358 ; 48.88,94.3 48.997,94.3 48.939,94.358 ; 48.88,94.3 48.939,94.358 ; 48.939,94.358 49.805,95.225 CN2.0@51.642,95.225 56.495,95.225 ; 56.495,95.225 CN2.0@61.342,95.225 61.342,92.771 ; 61.342,92.771 63.861,92.771 64.496,92.136 64.496,82.865 62.591,80.96 62.337,80.96
  TOP w1.27: P1.49@6.33,2.22 P1.50@8.87,2.22 20.808,2.22 23.348,4.76 ; P1.3@6.33,60.64 4.425,60.64 2.52,62.545 2.52,80.96 ; CN3.3@6.33,80.96 2.52,80.96 ; JP1.2@6.33,91.12 2.52,91.12 ; JP1.1@6.33,93.66 2.647,93.66 2.52,93.533 2.52,91.12 ; 32.365,2.22 P2.49@57.13,2.22 P2.50@59.67,2.22 ; 2.52,80.96 2.52,91.12
  Bottom w0.165: v1(28.936,83.627) 30.333,83.627 v1(30.333,84.516) ; v1(36.556,45.781) v1@36.556,45.908 ; 39.858,41.59 39.858,40.828 40.493,40.193 v1(40.493,40.066)
  Bottom w0.5: v1(16.363,60.64) 16.871,60.132 24.745,60.132 ; v1(16.617,64.577) 18.649,66.609 v1(24.745,66.609) 26.65,66.609 ; v1(17.76,56.449) v1(21.697,56.449) ; v1(19.411,42.606) 19.411,42.987 22.205,45.781 v1(26.904,45.781) ; v1(21.062,13.777) 30.714,23.429 v1(30.968,23.429) ; v1(21.851,70.929) 21.851,69.911 23.475,69.911 ; v1(23.475,77.912) 24.999,77.912 25.761,78.674 30.206,78.674 ; SB11.1@23.602,71.062 23.475,70.935 23.475,69.911 ; v1(24.364,69.911) 23.475,69.911 ; v1(24.745,57.846) 24.745,60.132 ; v1(24.745,62.545) 26.65,62.545 ; v1(30.333,62.926) 26.904,62.926 26.904,62.545 ; v1(30.714,69.53) 30.714,68.514 28.809,66.609 26.65,66.609 ; C38.2@31.044,76.531 31.095,76.531 v1(31.095,77.785) 31.095,78.674 30.206,78.674 ; v1(31.21,74.356) 30.46,74.356 30.079,74.737 30.079,77.15 30.714,77.785 30.333,77.785 30.333,78.547 30.206,78.674 ; v1(33.254,62.926) v1(36.81,62.926) 36.81,63.053 41.509,63.053 v1(41.509,62.799) v1@45.28,62.799 ; 33.381,57.846 33.381,57.592 29.698,57.592 29.698,58.227 29.635,58.29 v1(29.571,58.227) 26.904,58.227 v1(26.904,60.132) ; v1(33.762,73.975) 33.762,72.324 34.524,71.562 v1(34.524,70.673) ; v1@34.143,58.735 v1(34.27,58.735) v1@34.27,58.862 ; v1(35.159,73.34) 39.385,73.34 SB6.2@39.385,74.775 ; v1(36.556,45.781) 38.334,45.781 39.858,44.257 ; v1@36.556,45.908 36.556,51.242 ; 39.858,41.59 39.858,44.257 ; 40.493,44.257 39.858,44.257 ; SB19.1@41.39,50.48 39.985,50.48 39.223,51.242 36.556,51.242 ; v1(42.017,55.56) 41.255,55.56 39.731,54.036 37.191,54.036 36.556,53.401 36.556,51.242 ; v1(45.28,62.672) v1@45.28,62.799 ; v1@45.28,62.926 v1@45.28,62.799 ; v1(45.446,86.04) v1(51.542,86.04) ; 24.745,60.132 v1(26.904,60.132) ; 26.65,62.545 26.65,66.609 ; 26.65,62.545 26.904,62.545 ; v1(26.904,60.132) 26.904,62.545
LED_STLINK: R5.1 R6.1 U2.30 | length 27
  TOP w0.165: R5.1@19.665,88.361 19.665,87.658 19.839,87.484 v1@19.887,87.437 ; v1(19.792,87.437) v1@19.887,87.437 ; R6.1@20.936,88.355 20.936,87.437 v1@19.887,87.437 ; U2.30@34.86,77.065 36.26,77.065 v1(36.556,76.769)
  Bottom w0.165: v1(19.792,87.437) 19.792,86.675 25.507,80.96 31.603,80.96 33,79.563 34.524,79.563 36.556,77.531 v1(36.556,76.769)
MCO: C38.1 R48.2 SB12.1 | length 7.2
  Bottom w0.165: C38.1@31.044,75.331 32.289,75.331 R48.2@32.289,75.318 32.289,75.118 32.365,75.042 SB12.1@32.365,69.395
NetB1_2: B1.2 B1.3 C33.1 R4.2 R38.2 | length 76.8
  TOP w0.165: v1(10.267,70.673) 10.267,63.688 13.188,60.767 v1(13.188,52.766) ; v1(13.442,87.691) 13.569,87.691 13.608,87.73 R4.2@14.585,87.73 ; B1.3@15.75,32.41 18.395,32.41 ; C33.1@18.395,35.025 v1(18.395,33.97) ; R38.2@20.3,35.275 20.3,34.478 19.792,33.97 v1(18.395,33.97) ; B1.2@24.85,32.41 18.395,32.41 ; 18.395,32.41 v1(18.395,33.97)
  Bottom w0.165: v1(10.267,70.673) 8.616,70.673 8.235,71.054 8.235,82.484 v1(13.442,87.691) ; v1(13.188,52.766) 13.188,49.972 16.871,46.289 16.871,35.494 v1(18.395,33.97)
NetB2_1: B2.1 B2.4 C37.2 R39.1 SB23.2 | length 17.9
  TOP w0.165: v1(39.858,34.478) 40.493,35.113 C37.2@41.89,35.113 ; R39.1@43.795,35.44 43.795,35.19 C37.2@41.89,35.19 C37.2@41.89,35.113 ; B2.4@50.25,32.41 B2.1@41.15,32.41 41.15,33.484 41.89,34.224 C37.2@41.89,35.113
  Bottom w0.165: SB23.2@38.68,34.605 38.68,34.478 v1(39.858,34.478)
NetC1_2: C1.2 U1.4 | length 3.9
  TOP w0.5: U1.4@41.801,92.706 40.874,92.706 40.874,94.3 C1.2@42.301,94.3
NetC2_2: C2.2 C6.1 D3.1 U1.5 | length 9.6
  TOP w0.5: U1.5@41.801,90.806 40.814,90.806 40.747,90.739 40.747,89.212 C2.2@42.301,89.212 42.301,87.213 ; C6.1@42.301,84.767 42.301,87.213 ; D3.1@43.28,87.304 42.392,87.304 42.301,87.213
NetC14_1: C14.1 R29.2 X3.4 | length 5.3
  TOP w0.165: R29.2@40.585,65.885 41.598,65.885 41.903,65.58 X3.4@43.585,65.58 43.585,67.79 C14.1@43.58,67.79
NetC15_2: C15.2 U3.5 | length 2
  TOP w0.254: U3.5@58.904,72.197 58.904,73.35 C15.2@59.531,73.977
NetC16_1: C16.1 C17.2 R31.1 U4.21 | length 21.4
  TOP w0.165: 28.682,57.973 28.689,57.966 U4.21@28.689,56.502
  TOP w0.25: C16.1@21.316,64.45 C16.1@21.415,64.45 ; C17.2@24.872,63.6 26.142,62.33 26.142,59.497 26.904,58.735 27.92,58.735 28.682,57.973
  TOP w0.5: R31.1@15.855,63.78 15.855,65.466 16.617,66.228 18.776,66.228 20.554,64.45 C16.1@21.316,64.45 ; C16.1@21.415,64.45 22.84,64.45 23.69,63.6 C17.2@24.872,63.6
NetC20_1: C20.1 C21.2 L1.2 R31.2 U4.22 U4.100 | length 35.6
  TOP w0.165: U4.22@28.189,56.502 28.189,57.577
  TOP w0.25: R31.2@15.693,62.418 R31.2@15.855,62.58 ; C21.2@24.745,59.79 24.745,59.116 25.634,58.227 27.539,58.227 28.189,57.577 ; U4.22@28.189,56.502 28.189,53.132 28.682,52.639 31.476,52.639 31.603,52.512 37.699,52.512 38.334,53.147 38.334,53.528 39.358,54.552 U4.100@40.439,54.552
  TOP w0.5: L1.2@13.95,62.418 R31.2@15.693,62.418 ; R31.2@15.855,62.58 20.773,62.58 21.316,62.037 21.316,60.64 C20.1@21.415,60.64 22.713,60.64 23.563,59.79 C21.2@24.745,59.79
NetC22_2: C22.2 R32.2 X2.1 | length 5.4
  TOP w0.165: X2.1@29.181,65.08 28.301,64.2 C22.2@28.301,61.871 28.678,61.494 R32.2@29.952,61.494
NetC23_2: C23.2 R33.2 X2.2 | length 5.2
  TOP w0.165: R33.2@32.111,61.494 32.711,61.494 33.088,61.871 C23.2@33.762,61.871 33.762,62.672 34.261,63.171 X2.2@34.261,65.08
NetC24_1: C24.1 R34.1 U4.6 | length 5.5
  TOP w0.165: U4.6@36.189,56.502 36.189,58.622 36.81,59.243 C24.1@36.81,60.044 38.461,60.044 R34.1@38.461,60.04
NetC26_1: C26.1 R30.2 X3.1 | length 6.3
  TOP w0.165: R30.2@40.585,63.561 42.271,63.561 42.652,63.18 43.585,63.18 43.585,60.005 C26.1@43.58,60.005
NetC33_2: C33.2 R37.1 | length 2.4
  TOP w0.5: C33.2@18.395,36.725 R37.1@18.395,39.085
NetC36_2: C36.2 C39.1 U5.14 | length 3.8
  TOP w0.165: U5.14@34.021,32.325 34.021,33.862 C36.2@34.551,34.392 35.971,34.392 C39.1@36.01,34.353
NetC39_2: C39.2 R49.1 | length 1.7
  TOP w0.165: R49.1@37.31,36.004 37.31,34.453 C39.2@37.41,34.353
NetCN1_2: CN1.2 R14.1 | length 3.7
  TOP w0.165: CN1.2@33.797,90.275 33.797,87.529 34.27,87.056 R14.1@34.27,86.805
NetCN1_3: CN1.3 R12.1 R13.1 | length 5.5
  TOP w0.165: R12.1@31.73,86.805 31.73,87.437 32.111,87.818 32.997,87.818 ; CN1.3@32.997,90.275 32.997,87.818 ; R13.1@33,86.805 32.997,86.805 32.997,87.818
NetCN1_4: CN1.4 R11.1 | length 4.6
  TOP w0.165: R11.1@30.46,86.805 30.46,87.564 30.841,87.945 31.603,87.945 32.197,88.539 CN1.4@32.197,90.275
NetCN2_1: CN2.1 D4.1 | length 3.5
  TOP w0.5: CN2.1@58.092,90.275 58.092,88.761 59.035,87.818 D4.1@59.035,87.183
NetCN2_2: CN2.2 R18.1 | length 3.1
  TOP w0.165: R18.1@57.13,87.275 57.13,88.58 57.292,88.742 CN2.2@57.292,90.275
NetCN2_3: CN2.3 R16.1 R17.1 | length 4.5
  TOP w0.165: R16.1@54.59,87.275 R17.1@55.86,87.275 55.86,87.945 56.492,88.577 CN2.3@56.492,90.275
NetCN2_4: CN2.4 R15.1 | length 5.1
  TOP w0.165: R15.1@53.32,87.275 53.32,88.326 53.574,88.58 55.479,88.58 55.692,88.793 CN2.4@55.692,90.275
NetCN3_1: CN3.1 D1.1 R3.1 | length 8.5
  TOP w0.165: CN3.1@6.33,86.04 9.124,86.04 ; D1.1@10.267,86.04 9.124,86.04 ; R3.1@10.81,89.38 9.924,89.38 9.124,88.58 9.124,86.04
NetCN3_2: CN3.2 R19.1 | length 3.2
  TOP w0.165: CN3.2@6.33,83.5 R19.1@9.54,83.5
NetCN3_4: CN3.4 R20.1 | length 3.2
  TOP w0.165: CN3.4@6.33,78.42 R20.1@9.54,78.42
NetCN3_5: CN3.5 R21.1 | length 3.2
  TOP w0.165: CN3.5@6.33,75.88 R21.1@9.54,75.88
NetCN3_6: CN3.6 R22.1 | length 3.2
  TOP w0.165: CN3.6@6.33,73.34 R22.1@9.54,73.34
NetCN4_1: CN4.1 SB1.2 SB2.1 | length 14.8
  Bottom w0.165: SB2.1@40.485,79.855 CN4.1@47.605,79.855 SB1.2@55.26,79.855
NetCN4_2: CN4.2 SB3.2 SB4.1 | length 14.8
  Bottom w0.165: SB4.1@40.485,77.315 CN4.2@47.605,77.315 55.095,77.315 SB3.2@55.26,77.15
NetCN4_3: CN4.3 SB5.2 SB6.1 | length 14.8
  Bottom w0.165: SB6.1@40.485,74.775 CN4.3@47.605,74.775 SB5.2@55.26,74.775
NetCN4_4: CN4.4 SB8.2 SB9.1 | length 14.8
  Bottom w0.165: SB9.1@40.485,72.235 CN4.4@47.605,72.235 47.859,72.235 47.898,72.196 SB8.2@55.296,72.196
NetD1_2: D1.2 R7.1 | length 1.4
  TOP w0.165: D1.2@12.553,86.04 R7.1@13.985,86.04
NetD4_2: D4.2 D5.1 | length 1.9
  TOP w0.5: D4.2@59.035,84.897 D5.1@60.94,84.897
NetLD1_1: LD1.1 R1.1 | length 2
  TOP w0.165: LD1.1@12.045,91.705 13.703,91.705 R1.1@13.953,91.955
NetLD2_2: LD2.2 R6.2 | length 1.8
  TOP w0.165: R6.2@20.936,89.555 21.05,89.555 LD2.2@21.05,91.271
NetLD2_3: LD2.3 R5.2 | length 1.8
  TOP w0.165: LD2.3@19.55,91.271 19.55,90.263 19.665,90.263 R5.2@19.665,89.561
NetLD2_4: LD2.4 R2.1 | length 2.9
  TOP w0.165: R2.1@17.506,93.117 17.506,93.819 17.958,94.271 LD2.4@19.55,94.271
NetLD3_1: LD3.1 R41.1 | length 2.1
  TOP w0.165: R41.1@33,19.58 LD3.1@33,21.69
NetLD4_1: LD4.1 R40.1 | length 2.1
  TOP w0.165: LD4.1@27.315,19.335 R40.1@28.807,17.843
NetLD5_1: LD5.1 R42.1 | length 2.1
  TOP w0.165: R42.1@37.193,17.843 LD5.1@38.685,19.335
NetLD6_1: LD6.1 R43.1 | length 2.1
  TOP w0.165: LD6.1@24.96,13.65 R43.1@27.07,13.65
NetLD7_1: LD7.1 R44.1 | length 2.1
  TOP w0.165: R44.1@38.93,13.65 LD7.1@41.04,13.65
NetLD8_1: LD8.1 R45.1 | length 2.1
  TOP w0.165: LD8.1@27.315,7.965 R45.1@28.807,9.457
NetLD9_1: LD9.1 R47.1 | length 2.1
  TOP w0.165: R47.1@37.193,9.457 LD9.1@38.685,7.965
NetLD10_1: LD10.1 R46.1 | length 2.1
  TOP w0.165: LD10.1@33,5.61 R46.1@33,7.72
NetP2_41: P2.41 SB21.2 | length 26.1
  Bottom w0.165: SB21.2@46.97,34.005 46.97,22.032 56.622,12.38 P2.41@57.13,12.38
NetP2_42: P2.42 SB22.1 | length 31.6
  Bottom w0.165: SB22.1@45.092,34.107 45.092,33.816 46.335,32.573 46.335,22.032 55.733,12.634 55.733,11.618 56.241,11.11 58.4,11.11 P2.42@59.67,12.38
NetR8_2: R8.2 U2.3 | length 9.7
  TOP w0.165: U2.3@26.06,79.065 24.872,79.065 24.364,79.573 24.364,84.77 25.199,85.605 R8.2@26.65,85.605
NetR9_2: R9.2 U2.2 | length 9.8
  TOP w0.165: U2.2@26.06,79.565 24.997,79.565 24.745,79.817 24.745,83.881 25.507,84.643 27.666,84.643 27.92,84.897 R9.2@27.92,85.605
NetR10_2: R10.2 U2.44 | length 4.1
  TOP w0.165: R10.2@29.19,85.605 29.19,84.643 29.71,84.123 U2.44@29.71,81.715
NetR35_1: R35.1 SB19.2 | length 2.6
  TOP w0.165: v1(43.668,50.48) 43.668,50.445 R35.1@45.065,50.445
  Bottom w0.165: SB19.2@42.49,50.48 v1(43.668,50.48)
NetR38_1: R38.1 SB20.2 | length 2.8
  TOP w0.165: v1(19.538,37.526) 20.046,37.526 20.3,37.272 R38.1@20.3,36.475
  Bottom w0.165: SB20.2@18.522,37.18 18.868,37.526 v1(19.538,37.526)
NetR48_1: R48.1 U2.29 | length 2.6
  TOP w0.165: v1(33.381,76.515) 33.381,76.565 U2.29@34.86,76.565
  Bottom w0.165: R48.1@32.289,76.518 32.289,76.515 v1(33.381,76.515)
NRST: P1.4 SB7.2 SB23.1 U4.14 | length 67
  TOP w0.165: P1.4@8.87,60.64 7.727,61.783 7.727,67.371 8.616,68.26 8.616,70.927 v1(9.124,71.435) ; U4.14@32.189,56.502 32.189,55.355 32.619,54.925 v1(32.619,54.163)
  Bottom w0.165: P1.4@8.87,60.64 10.902,58.608 22.586,58.608 24.237,56.957 29.063,56.957 29.698,56.322 31.476,56.322 32.746,55.052 32.746,54.163 v1(32.619,54.163) 32.619,45.908 34.651,43.876 34.651,39.812 34.905,39.558 34.905,36.51 36.81,34.605 SB23.1@37.58,34.605 ; v1(9.124,71.435) 9.124,74.194 SB7.2@9.54,74.61
OSC_IN: C7.2 U2.5 X1.2 | length 13
  TOP w0.165: U2.5@26.06,78.065 25.1,78.065 23.729,79.436 20.935,79.436 19.67,80.701 X1.2@19.67,81.751 17.633,81.751 17.442,81.56 C7.2@15.893,81.56 ; C7.2@15.838,81.468 15.838,81.577 C7.2@15.855,81.56 C7.2@15.893,81.56 ; C7.2@15.838,81.468 15.883,81.543 C7.2@15.893,81.56 ; C7.2@15.838,81.468 15.83,81.455 15.83,81.624 15.932,81.624 C7.2@15.893,81.56
OSC_OUT: C9.2 U2.6 X1.1 | length 12.2
  TOP w0.165: C9.2@15.855,76.55 16.998,76.55 17.119,76.671 X1.1@19.67,76.671 19.67,78.044 20.173,78.547 23.729,78.547 24.711,77.565 U2.6@26.06,77.565
PA0: P1.12 SB20.1 U4.23 | length 43.1
  TOP w0.165: P1.12@8.87,50.48 8.997,50.48 9.251,50.226 v1(13.823,50.226) ; v1(27.539,53.782) 27.689,53.932 U4.23@27.689,56.502
  Bottom w0.165: P1.12@8.87,50.48 9.378,50.48 9.378,50.861 10.521,52.004 10.521,53.147 11.664,54.29 26.142,54.29 26.65,53.782 v1(27.539,53.782) ; v1(13.823,50.226) 17.506,46.543 17.506,40.828 18.522,39.812 SB20.1@18.522,38.28
PA1: P1.9 U4.24 | length 25.2
  TOP w0.165: v1(27.031,54.417) 27.031,55.56 27.164,55.692 27.164,56.502 U4.24@27.189,56.502
  Bottom w0.165: P1.9@6.33,53.02 7.524,51.826 9.581,51.826 10.14,52.385 10.14,53.274 11.537,54.671 26.777,54.671 v1(27.031,54.417)
PA2: P1.14 U4.25 | length 25.3
  TOP w0.165: v1(26.396,53.147) 26.396,55.052 26.689,55.345 U4.25@26.689,56.302
  Bottom w0.165: P1.14@8.87,47.94 10.394,49.464 10.394,51.242 10.902,51.75 10.902,52.893 11.918,53.909 25.634,53.909 v1(26.396,53.147)
PA3: P1.11 U4.26 | length 26.8
  TOP w0.165: P1.11@6.33,50.48 7.6,49.21 13.696,49.21 15.093,50.607 15.093,55.814 16.744,57.465 19.792,57.465 22.705,54.552 U4.26@24.939,54.552
PA4: P1.16 U4.29 | length 19
  TOP w0.165: P1.16@8.87,45.4 10.212,45.4 11.791,45.4 18.256,51.865 21.406,51.865 22.593,53.052 U4.29@24.739,53.052
PA5: P1.15 U4.30 U5.2 | length 48.7
  TOP w0.165: P1.15@6.33,45.4 7.654,44.077 10.913,44.077 18.302,51.465 21.608,51.465 22.696,52.552 U4.30@24.939,52.552 25.594,52.552 27.158,50.988 27.158,49.972 v1(27.412,49.718) ; v1(30.079,30.922) 30.079,30.85 U5.2@31.896,30.85
  Bottom w0.165: v1(27.412,49.718) 28.682,48.448 28.682,37.907 29.825,36.764 29.825,31.176 v1(30.079,30.922)
PA6: P1.18 U4.31 U5.4 | length 46.9
  TOP w0.165: P1.18@8.87,42.86 9.612,42.86 10.142,42.86 18.347,51.065 21.709,51.065 22.696,52.052 U4.31@24.939,52.052 25.586,52.052 26.777,50.861 26.777,49.464 v1(27.539,48.702) ; v1(29.952,29.525) 29.927,29.55 U5.4@31.896,29.55
  Bottom w0.165: v1(27.539,48.702) 28.301,47.94 28.301,37.272 29.444,36.129 29.444,30.033 v1(29.952,29.525)
PA7: P1.17 U4.32 U5.3 | length 49.9
  TOP w0.165: P1.17@6.33,42.86 7.52,41.628 9.356,41.628 18.393,50.665 21.809,50.665 22.696,51.552 25.578,51.552 26.396,50.734 26.396,48.702 v1(27.412,47.686) ; v1(28.682,30.287) 28.769,30.2 U5.3@31.896,30.2
  Bottom w0.165: v1(27.412,47.686) 27.92,47.178 27.92,37.018 28.936,36.002 28.936,32.954 28.682,32.7 v1(28.682,30.287)
PA8: P2.45 U4.67 | length 45.6
  TOP w0.165: U4.67@34.689,40.602 34.689,37.742 35.413,37.018 v1(35.54,37.018)
  Bottom w0.165: v1(35.54,37.018) 37.064,35.494 40.874,35.494 42.017,34.351 42.017,27.366 44.303,25.08 44.303,18.857 55.86,7.3 P2.45@57.13,7.3
PA9: P2.44 U4.68 | length 46.9
  TOP w0.165: U4.68@35.189,40.602 35.159,40.602 35.159,38.288 v1(35.54,37.907)
  Bottom w0.165: v1(35.54,37.907) 37.572,35.875 41.128,35.875 42.398,34.605 42.398,27.62 44.811,25.207 44.811,19.746 55.86,8.697 58.527,8.697 P2.44@59.67,9.84
PA10: P2.43 U4.69 | length 46
  TOP w0.165: v1(35.286,42.225) 35.689,41.822 U4.69@35.689,40.802 U4.69@35.689,40.602
  Bottom w0.165: v1(35.286,42.225) 35.286,39.05 36.175,38.161 36.175,37.907 37.826,36.256 41.509,36.256 42.779,34.986 42.779,27.874 45.319,25.334 45.319,20.508 55.987,9.84 P2.43@57.13,9.84
PA11: R18.2 SB22.2 U4.70 | length 69
  TOP w0.165: U4.70@36.189,40.602 36.189,39.544 v1(37.445,38.288) ; v1(46.335,37.145) 46.843,37.145 50.526,40.828 50.526,59.751 51.034,60.259 51.034,67.244 50.399,67.879 50.399,77.658 57.13,84.389 R18.2@57.13,86.075
  Bottom w0.165: v1(37.445,38.288) 38.207,37.526 45.954,37.526 v1(46.335,37.145) 46.208,37.145 45.092,36.029 SB22.2@45.092,35.207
